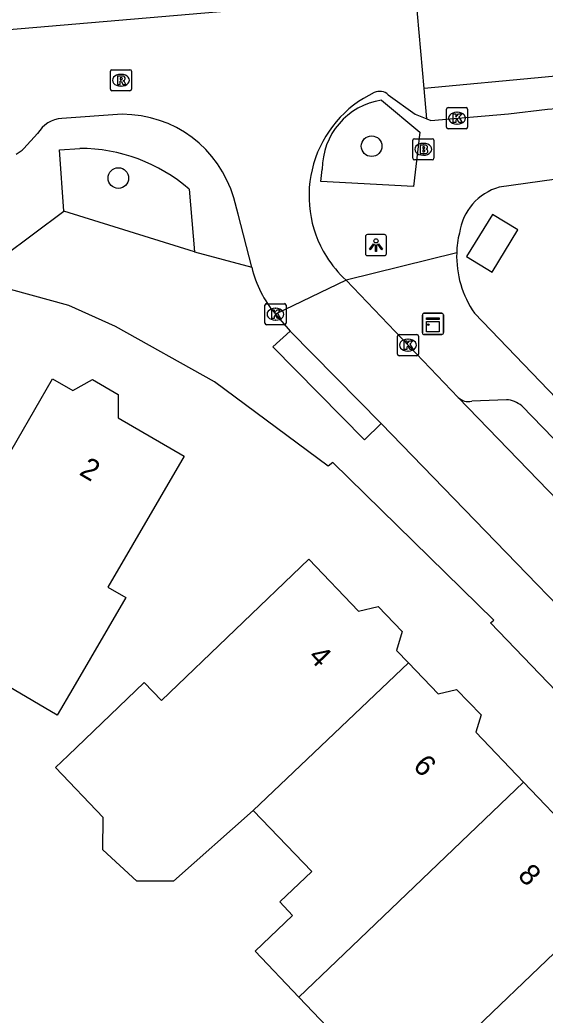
# Model space of a CAD drawing. Extents: x 161772 to 163123, y 383092 to 383917.
# Drawn here: x 162102.59 to 162127.51, y 383436.5 to 383483.68 of the extents above; entities that cross this region are included whole.
import ezdxf

# ---------------------------------------------------------------- set-up
doc = ezdxf.new("R2010")
doc.units = 0
for name, color, linetype in [('IMGEO_Boom', 7, 'Continuous'), ('IMGEO_Brandkraan', 7, 'Continuous'), ('IMGEO_Kast', 7, 'Continuous'), ('IMGEO_Kolk', 7, 'Continuous'), ('IMGEO_Lichtpunt', 7, 'Continuous'), ('IMGEO_Pand', 7, 'Continuous'), ('IMGEO_Pand_nummerreeks', 7, 'Continuous'), ('IMGEO_Rijbaan_lokaal_gesloten', 7, 'Continuous'), ('IMGEO_Rijbaan_lokaal_open', 7, 'Continuous'), ('IMGEO_Rioolput', 7, 'Continuous'), ('IMGEO_Voetpad_gesloten', 7, 'Continuous'), ('IMGEO_Voetpad_open', 7, 'Continuous')]:
    doc.layers.add(name, color=color, linetype=linetype)

msp = doc.modelspace()

# ---------------------------------------------------------------- linework, layer by layer
at = {"layer": 'IMGEO_Boom'}
for centre in [(162119.275, 383477.692), (162107.26, 383476.18)]:
    msp.add_circle(centre, 0.489, dxfattribs=at)
at = {"layer": 'IMGEO_Brandkraan'}
for p, q in [((162121.228, 383477.118), (162121.228, 383477.97)), ((162121.303, 383478.044), (162122.155, 383478.044)), ((162122.229, 383477.97), (162122.229, 383477.118)), ((162121.716, 383477.824), (162121.741, 383477.824)), ((162122.155, 383477.044), (162121.303, 383477.044)), ((162121.739, 383477.264), (162121.714, 383477.264))]:
    msp.add_line(p, q, dxfattribs=at)
for points in [[(162121.228, 383477.118), (162121.228, 383477.97)], [(162121.303, 383478.044), (162122.155, 383478.044)], [(162122.229, 383477.97), (162122.229, 383477.118)], [(162121.576, 383477.744), (162121.576, 383477.344), (162121.789, 383477.344)], [(162121.807, 383477.744), (162121.576, 383477.744)], [(162121.755, 383477.663), (162121.701, 383477.663), (162121.701, 383477.587)], [(162121.701, 383477.587), (162121.754, 383477.587)], [(162121.763, 383477.511), (162121.701, 383477.511), (162121.701, 383477.43)], [(162122.155, 383477.044), (162121.303, 383477.044)], [(162121.701, 383477.43), (162121.763, 383477.43)]]:
    msp.add_lwpolyline(points, dxfattribs=at)
for centre, radius, start, end in [((162121.305, 383477.968), 0.0765, 91.552, 178.448), ((162121.305, 383477.968), 0.0765, 91.552, 178.448), ((162122.153, 383477.968), 0.0765, 1.552, 88.448), ((162122.153, 383477.968), 0.0765, 1.552, 88.448), ((162121.756, 383477.625), 0.0379, 267.8285, 90.9355), ((162121.764, 383477.47), 0.0404, 269.8759, 90.5077), ((162121.811, 383477.599), 0.145, 59.4692, 91.5367), ((162121.836, 383477.646), 0.0922, 285.5137, 58.1501), ((162121.841, 383477.454), 0.105, 301.3115, 78.989), ((162121.305, 383477.12), 0.0765, 181.552, 268.448), ((162121.305, 383477.12), 0.0765, 181.552, 268.448), ((162121.795, 383477.595), 0.251, 268.6676, 293.5347), ((162122.153, 383477.12), 0.0765, 271.552, 358.448), ((162122.153, 383477.12), 0.0765, 271.552, 358.448)]:
    msp.add_arc(centre, radius, start, end, dxfattribs=at)
for centre, major_axis, ratio, start_param, end_param in [((162121.715, 383477.544), (-0.387, 0.002), 0.722429, 4.712389, 7.853982), ((162121.74, 383477.544), (-0.39, 0.002), 0.717154, 1.570796, 4.712389)]:
    msp.add_ellipse(centre, major_axis=major_axis, ratio=ratio, start_param=start_param, end_param=end_param, dxfattribs=at)
at = {"layer": 'IMGEO_Kast'}
for p, q in [((162121.685, 383468.843), (162121.685, 383469.684)), ((162121.685, 383469.684), (162121.685, 383468.843)), ((162121.76, 383469.768), (162122.601, 383469.768)), ((162122.601, 383469.768), (162121.76, 383469.768)), ((162122.685, 383469.693), (162122.685, 383468.852)), ((162122.685, 383468.852), (162122.685, 383469.693)), ((162122.61, 383468.768), (162121.769, 383468.768)), ((162121.769, 383468.768), (162122.61, 383468.768))]:
    msp.add_line(p, q, dxfattribs=at)
for points in [[(162121.88, 383469.558), (162122.48, 383469.558), (162122.48, 383469.473), (162121.88, 383469.473), (162121.88, 383469.558)], [(162121.88, 383469.383), (162122.48, 383469.383), (162122.48, 383468.894), (162121.88, 383468.894), (162121.88, 383469.383)]]:
    msp.add_lwpolyline(points, dxfattribs=at)
msp.add_circle((162121.964, 383469.232), 0.0377, dxfattribs=at)
for centre, start, end in [((162121.763, 383469.69), 92.4484, 184.2845), ((162121.763, 383469.69), 92.4484, 184.2845), ((162122.607, 383469.69), 2.4484, 94.2845), ((162122.607, 383469.69), 2.4484, 94.2845), ((162121.763, 383468.846), 182.4484, 274.2845), ((162121.763, 383468.846), 182.4484, 274.2845), ((162122.607, 383468.846), 272.4484, 4.2845), ((162122.607, 383468.846), 272.4484, 4.2845)]:
    msp.add_arc(centre, 0.0779, start, end, dxfattribs=at)
at = {"layer": 'IMGEO_Kolk'}
for p, q in [((162122.828, 383478.596), (162122.828, 383479.448)), ((162122.903, 383479.522), (162123.755, 383479.522)), ((162123.829, 383479.448), (162123.829, 383478.596)), ((162123.316, 383479.302), (162123.341, 383479.302)), ((162123.755, 383478.522), (162122.903, 383478.522)), ((162123.339, 383478.742), (162123.314, 383478.742)), ((162114.214, 383469.3), (162114.214, 383470.152)), ((162114.289, 383470.226), (162115.141, 383470.226)), ((162114.702, 383470.006), (162114.727, 383470.006)), ((162115.215, 383470.152), (162115.215, 383469.3)), ((162114.725, 383469.446), (162114.7, 383469.446)), ((162115.141, 383469.226), (162114.289, 383469.226)), ((162120.501, 383467.833), (162120.501, 383468.685)), ((162120.576, 383468.759), (162121.428, 383468.759)), ((162120.989, 383468.539), (162121.014, 383468.539)), ((162121.502, 383468.685), (162121.502, 383467.833)), ((162121.428, 383467.759), (162120.576, 383467.759)), ((162121.012, 383467.979), (162120.987, 383467.979))]:
    msp.add_line(p, q, dxfattribs=at)
for points in [[(162122.828, 383478.596), (162122.828, 383479.448)], [(162122.903, 383479.522), (162123.755, 383479.522)], [(162123.829, 383479.448), (162123.829, 383478.596)], [(162123.149, 383479.222), (162123.272, 383479.222), (162123.272, 383479.071), (162123.402, 383479.222), (162123.566, 383479.222), (162123.42, 383479.071), (162123.573, 383478.822), (162123.421, 383478.822), (162123.336, 383478.986), (162123.272, 383478.919), (162123.272, 383478.822), (162123.149, 383478.822), (162123.149, 383479.222)], [(162123.755, 383478.522), (162122.903, 383478.522)], [(162114.214, 383469.3), (162114.214, 383470.152)], [(162114.289, 383470.226), (162115.141, 383470.226)], [(162114.535, 383469.926), (162114.658, 383469.926), (162114.658, 383469.775), (162114.788, 383469.926), (162114.952, 383469.926), (162114.806, 383469.775), (162114.959, 383469.526), (162114.807, 383469.526), (162114.722, 383469.69), (162114.658, 383469.623), (162114.658, 383469.526), (162114.535, 383469.526), (162114.535, 383469.926)], [(162115.215, 383470.152), (162115.215, 383469.3)], [(162115.141, 383469.226), (162114.289, 383469.226)], [(162120.501, 383467.833), (162120.501, 383468.685)], [(162120.576, 383468.759), (162121.428, 383468.759)], [(162121.502, 383468.685), (162121.502, 383467.833)], [(162120.822, 383468.459), (162120.945, 383468.459), (162120.945, 383468.308), (162121.075, 383468.459), (162121.239, 383468.459), (162121.093, 383468.308), (162121.246, 383468.059), (162121.094, 383468.059), (162121.009, 383468.223), (162120.945, 383468.156), (162120.945, 383468.059), (162120.822, 383468.059), (162120.822, 383468.459)], [(162121.428, 383467.759), (162120.576, 383467.759)]]:
    msp.add_lwpolyline(points, dxfattribs=at)
for centre, start, end in [((162122.905, 383479.446), 91.552, 178.448), ((162122.905, 383479.446), 91.552, 178.448), ((162123.753, 383479.446), 1.552, 88.448), ((162123.753, 383479.446), 1.552, 88.448), ((162122.905, 383478.598), 181.552, 268.448), ((162122.905, 383478.598), 181.552, 268.448), ((162123.753, 383478.598), 271.552, 358.448), ((162123.753, 383478.598), 271.552, 358.448), ((162114.291, 383470.15), 91.552, 178.448), ((162114.291, 383470.15), 91.552, 178.448), ((162115.139, 383470.15), 1.552, 88.448), ((162115.139, 383470.15), 1.552, 88.448), ((162114.291, 383469.302), 181.552, 268.448), ((162114.291, 383469.302), 181.552, 268.448), ((162115.139, 383469.302), 271.552, 358.448), ((162115.139, 383469.302), 271.552, 358.448), ((162120.578, 383468.683), 91.552, 178.448), ((162120.578, 383468.683), 91.552, 178.448), ((162121.426, 383468.683), 1.552, 88.448), ((162121.426, 383468.683), 1.552, 88.448), ((162120.578, 383467.835), 181.552, 268.448), ((162120.578, 383467.835), 181.552, 268.448), ((162121.426, 383467.835), 271.552, 358.448), ((162121.426, 383467.835), 271.552, 358.448)]:
    msp.add_arc(centre, 0.0765, start, end, dxfattribs=at)
for centre, major_axis, ratio, start_param, end_param in [((162123.315, 383479.022), (-0.387, 0.002), 0.722429, 4.712389, 7.853982), ((162123.34, 383479.022), (-0.39, 0.002), 0.717154, 1.570796, 4.712389), ((162114.701, 383469.726), (-0.387, 0.002), 0.722429, 4.712389, 7.853982), ((162114.726, 383469.726), (-0.39, 0.002), 0.717154, 1.570796, 4.712389), ((162120.988, 383468.259), (-0.387, 0.002), 0.722429, 4.712389, 7.853982), ((162121.013, 383468.259), (-0.39, 0.002), 0.717154, 1.570796, 4.712389)]:
    msp.add_ellipse(centre, major_axis=major_axis, ratio=ratio, start_param=start_param, end_param=end_param, dxfattribs=at)
at = {"layer": 'IMGEO_Lichtpunt'}
for p, q in [((162118.984, 383473.406), (162118.984, 383472.599)), ((162118.984, 383473.406), (162118.984, 383472.599)), ((162119.886, 383473.501), (162119.078, 383473.501)), ((162119.886, 383473.501), (162119.078, 383473.501)), ((162119.98, 383472.599), (162119.98, 383473.406)), ((162119.98, 383472.599), (162119.98, 383473.406)), ((162119.078, 383472.505), (162119.886, 383472.505)), ((162119.078, 383472.505), (162119.886, 383472.505))]:
    msp.add_line(p, q, dxfattribs=at)
for points in [[(162119.358, 383473.07), (162119.397, 383473.042), (162119.209, 383472.78), (162119.171, 383472.807), (162119.358, 383473.07)], [(162119.46, 383473.022), (162119.507, 383473.022), (162119.507, 383472.7), (162119.46, 383472.7), (162119.46, 383473.022)], [(162119.57, 383473.042), (162119.608, 383473.069), (162119.795, 383472.807), (162119.756, 383472.779), (162119.57, 383473.042)]]:
    msp.add_lwpolyline(points, dxfattribs=at)
msp.add_circle((162119.483, 383473.204), 0.0994, dxfattribs=at)
for centre, start, end in [((162119.078, 383473.406), 90, 180), ((162119.078, 383473.406), 90, 180), ((162119.886, 383473.406), 0, 90), ((162119.886, 383473.406), 0, 90), ((162119.078, 383472.599), 180, 270), ((162119.078, 383472.599), 180, 270), ((162119.886, 383472.599), 270, 0), ((162119.886, 383472.599), 270, 360)]:
    msp.add_arc(centre, 0.0946, start, end, dxfattribs=at)
at = {"layer": 'IMGEO_Pand'}
for points in [[(162123.783, 383472.466), (162124.99, 383471.726), (162126.213, 383473.719), (162125.006, 383474.459), (162123.783, 383472.466)], [(162097.887, 383455.933), (162101.601, 383462.305), (162104.142, 383466.664), (162105.107, 383466.102), (162106.029, 383466.629), (162107.248, 383465.919), (162107.244, 383464.819), (162110.378, 383462.992), (162106.764, 383456.792), (162107.614, 383456.296), (162105.096, 383451.977), (162104.364, 383450.721), (162100.874, 383452.756), (162101.499, 383453.827), (162097.887, 383455.933)], [(162113.662, 383446.203), (162109.869, 383442.847), (162108.131, 383442.847), (162106.518, 383444.337), (162106.536, 383445.869), (162104.275, 383448.232), (162104.875, 383448.806), (162108.488, 383452.261), (162109.3, 383451.412), (162116.3, 383458.108), (162118.656, 383455.644), (162119.588, 383455.872), (162120.722, 383454.686), (162120.46, 383453.787), (162121.024, 383453.197)], [(162121.024, 383453.197), (162113.662, 383446.203)], [(162121.024, 383453.197), (162122.432, 383451.725), (162123.31, 383451.939), (162124.467, 383450.73), (162124.226, 383449.903), (162126.489, 383447.537)], [(162126.489, 383447.537), (162128.901, 383445.016), (162129.787, 383445.232), (162130.649, 383444.331), (162130.623, 383443.167), (162131.203, 383442.561), (162127.59, 383439.105), (162124.25, 383435.91), (162120.731, 383432.225), (162117.835, 383435.252), (162115.829, 383437.349)], [(162115.829, 383437.349), (162117.608, 383439.049), (162126.489, 383447.537)], [(162115.829, 383437.349), (162113.752, 383439.52), (162115.53, 383441.221), (162114.92, 383441.859), (162116.433, 383443.306), (162113.662, 383446.203)]]:
    msp.add_lwpolyline(points, dxfattribs=at)
at = {"layer": 'IMGEO_Rijbaan_lokaal_gesloten'}
msp.add_lwpolyline([(162213.84, 383494.742), (162208.551, 383493.75), (162191.634, 383490.333), (162176.787, 383487.642), (162172.161, 383486.674), (162151.828, 383483.337), (162127.505, 383480.969), (162121.767, 383480.433)], dxfattribs=at)
at = {"layer": 'IMGEO_Rijbaan_lokaal_open'}
for points in [[(162121.373, 383484.872), (162101.898, 383483.2)], [(162121.767, 383480.433), (162121.373, 383484.872)], [(162121.895, 383478.988), (162121.767, 383480.433)], [(162120.064, 383480.126), (162121.341, 383479.204), (162121.895, 383478.988)], [(162107.446, 383479.204), (162104.576, 383479.011)], [(162103.43, 383478.296), (162102.77, 383477.59)], [(162113.593, 383471.954), (162112.938, 383474.463), (162112.736, 383475.236)], [(162118.063, 383471.34), (162114.715, 383469.726)], [(162123.379, 383465.784), (162118.063, 383471.34)], [(162114.715, 383469.726), (162115.405, 383468.922)], [(162115.405, 383468.922), (162119.726, 383464.542)], [(162139.993, 383448.624), (162123.379, 383465.784)], [(162119.726, 383464.542), (162135.053, 383448.745)]]:
    msp.add_lwpolyline(points, dxfattribs=at)
for centre, radius, start, end in [((162119.654, 383479.702), 0.59, 45.9709, 115.5526), ((162121.729, 383475.337), 5.423, 115.4366, 211.9745), ((162104.677, 383477.573), 1.441, 94.0213, 149.8996), ((162107.461, 383473.714), 5.49, 16.0987, 90.1546), ((162101.839, 383478.442), 1.263, 296.7578, 317.5355), ((162121.743, 383475.345), 5.439, 211.9755, 227.4249), ((162118.676, 383473.117), 5.214, 192.8893, 220.5695)]:
    msp.add_arc(centre, radius, start, end, dxfattribs=at)
at = {"layer": 'IMGEO_Rioolput'}
for p, q in [((162106.883, 383480.393), (162106.883, 383481.245)), ((162106.958, 383481.319), (162107.81, 383481.319)), ((162107.884, 383481.245), (162107.884, 383480.393)), ((162107.371, 383481.099), (162107.396, 383481.099)), ((162107.81, 383480.319), (162106.958, 383480.319)), ((162107.394, 383480.539), (162107.369, 383480.539))]:
    msp.add_line(p, q, dxfattribs=at)
for points in [[(162106.883, 383480.393), (162106.883, 383481.245)], [(162106.958, 383481.319), (162107.81, 383481.319)], [(162107.884, 383481.245), (162107.884, 383480.393)], [(162107.472, 383481.017), (162107.22, 383481.019), (162107.22, 383480.619)], [(162107.22, 383480.619), (162107.344, 383480.619), (162107.344, 383480.781), (162107.355, 383480.781)], [(162107.398, 383480.938), (162107.344, 383480.938), (162107.344, 383480.857)], [(162107.344, 383480.857), (162107.396, 383480.857)], [(162107.402, 383480.752), (162107.473, 383480.619), (162107.613, 383480.619), (162107.548, 383480.745)], [(162107.81, 383480.319), (162106.958, 383480.319)]]:
    msp.add_lwpolyline(points, dxfattribs=at)
for centre, radius, start, end in [((162106.96, 383481.243), 0.0765, 91.552, 178.448), ((162106.96, 383481.243), 0.0765, 91.552, 178.448), ((162107.808, 383481.243), 0.0765, 1.552, 88.448), ((162107.808, 383481.243), 0.0765, 1.552, 88.448), ((162107.354, 383480.728), 0.0533, 26.0293, 88.6989), ((162107.38, 383481.046), 0.19, 274.7715, 282.9687), ((162107.404, 383480.842), 0.0964, 77.0061, 93.1865), ((162107.418, 383480.899), 0.0378, 276.6634, 79.6772), ((162107.471, 383480.907), 0.109, 350.3612, 89.416), ((162107.469, 383480.907), 0.112, 277.5842, 350.9817), ((162107.453, 383480.692), 0.108, 29.5134, 73.7905), ((162106.96, 383480.395), 0.0765, 181.552, 268.448), ((162106.96, 383480.395), 0.0765, 181.552, 268.448), ((162107.808, 383480.395), 0.0765, 271.552, 358.448), ((162107.808, 383480.395), 0.0765, 271.552, 358.448)]:
    msp.add_arc(centre, radius, start, end, dxfattribs=at)
for centre, major_axis, ratio, start_param, end_param in [((162107.37, 383480.819), (-0.387, 0.002), 0.722429, 4.712389, 7.853982), ((162107.395, 383480.819), (-0.39, 0.002), 0.717154, 1.570796, 4.712389)]:
    msp.add_ellipse(centre, major_axis=major_axis, ratio=ratio, start_param=start_param, end_param=end_param, dxfattribs=at)
at = {"layer": 'IMGEO_Voetpad_gesloten'}
for points in [[(162104.678, 383474.608), (162104.467, 383477.512), (162105.425, 383477.589)], [(162110.627, 383475.653), (162110.865, 383472.685)], [(162100.337, 383471.381), (162104.678, 383474.608)], [(162110.865, 383472.685), (162104.678, 383474.608)], [(162110.865, 383472.685), (162113.593, 383471.954)], [(162123.312, 383472.633), (162118.063, 383471.34)], [(162184.032, 383393.274), (162150.539, 383428.274), (162150.594, 383428.39), (162124.921, 383455.092), (162125.07, 383455.226), (162117.429, 383462.692), (162117.208, 383462.523), (162111.823, 383466.516), (162107.132, 383469.149), (162104.903, 383470.142), (162100.337, 383471.381)], [(162124.151, 383469.777), (162146.748, 383446.299), (162164.511, 383427.931), (162164.384, 383427.827), (162167.143, 383425.007), (162167.165, 383425.116), (162173.798, 383418.361), (162173.894, 383418.482), (162182.621, 383409.404), (162182.533, 383409.335), (162187.734, 383404.146), (162187.816, 383404.232), (162192.761, 383399.098), (162192.872, 383399.214), (162225.52, 383365.058), (162237.143, 383353.041), (162243.372, 383346.601)], [(162119.726, 383464.542), (162118.937, 383463.776), (162114.594, 383468.182), (162115.405, 383468.922)], [(162125.671, 383465.674), (162124.028, 383465.597)], [(162141.362, 383449.954), (162126.398, 383465.384)]]:
    msp.add_lwpolyline(points, dxfattribs=at)
for centre, radius, start, end in [((162105.419, 383469.617), 7.972, 49.2146, 89.9584), ((162128.036, 383472.469), 4.726, 178.0161, 214.7261), ((162123.88, 383466.304), 0.722, 226.0347, 281.8181), ((162125.583, 383464.397), 1.28, 50.4543, 86.0517)]:
    msp.add_arc(centre, radius, start, end, dxfattribs=at)
at = {"layer": 'IMGEO_Voetpad_open'}
for points in [[(162216.905, 383490.741), (162172.706, 383482.249), (162150.151, 383478.81), (162136.452, 383477.299), (162125.335, 383475.754)], [(162121.895, 383478.988), (162122.088, 383478.913), (162125.763, 383479.233), (162127.621, 383479.441), (162129.321, 383479.57), (162138.962, 383480.496), (162145.47, 383481.185)], [(162119.748, 383479.869), (162121.567, 383478.36)], [(162121.567, 383478.36), (162121.265, 383475.788), (162116.87, 383476.014), (162116.935, 383476.593)]]:
    msp.add_lwpolyline(points, dxfattribs=at)
for centre, radius, start, end in [((162120.227, 383476.612), 3.292, 98.3649, 180.3318), ((162126.069, 383473.202), 2.655, 106.0501, 171.9773), ((162127.973, 383472.477), 4.664, 166.408, 178.0834)]:
    msp.add_arc(centre, radius, start, end, dxfattribs=at)

# ---------------------------------------------------------------- texts
at = {"layer": 'IMGEO_Pand_nummerreeks'}
for s, rotation, p in [('2', 329.5088, (162105.356, 383462.143)), ('4', 313.7884, (162116.225, 383453.446)), ('6', 313.7884, (162121.193, 383448.264)), ('8', 313.7884, (162126.164, 383443.078))]:
    msp.add_text(s, height=1, rotation=rotation, dxfattribs=at).set_placement(p)

doc.saveas('drawing.dxf')
